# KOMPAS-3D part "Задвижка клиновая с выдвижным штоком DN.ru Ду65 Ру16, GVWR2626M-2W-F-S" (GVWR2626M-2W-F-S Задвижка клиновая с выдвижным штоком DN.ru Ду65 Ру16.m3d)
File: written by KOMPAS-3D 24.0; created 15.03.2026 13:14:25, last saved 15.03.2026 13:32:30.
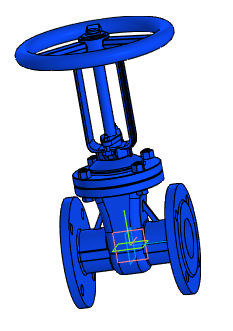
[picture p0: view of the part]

Document properties: Автор: R2D2; Полное имя файла: E:\Работа\Зайцев\GVWR2626M-2W-F-S Задвижка клиновая с выдвижным штоком DN.ru Ду50-300 Ру16\DN65\GVWR2626M-2W-F-S Задвижка клиновая с выдвижным штоком DN.ru Ду65 Ру16.m3d

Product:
- Part/product: Задвижка клиновая с выдвижным штоком DN.ru Ду65 Ру16  | designation GVWR2626M-2W-F-S
    Масса: 18
    Раздел спецификации: Прочие изделия
    Примечание: D040-10500

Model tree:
1. Операция без истории:1

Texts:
  GVWR2626M-2W-F-S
